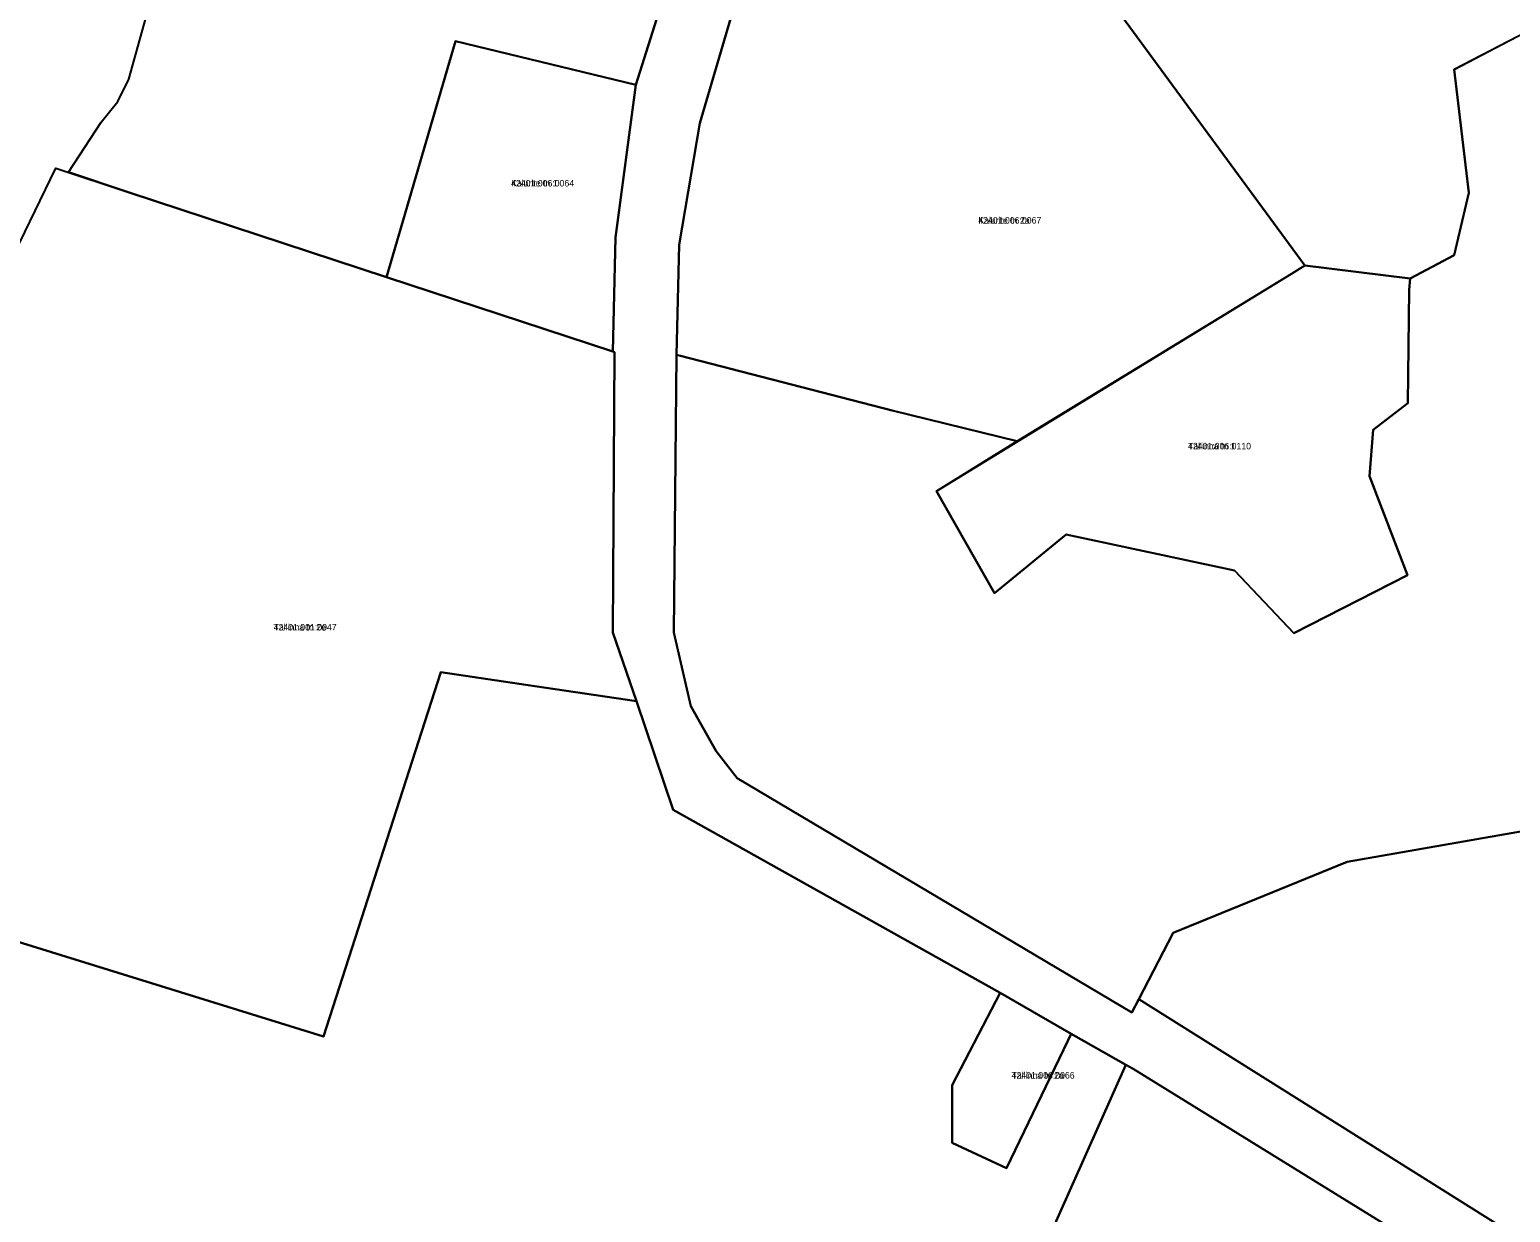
# Model space of a CAD drawing. Extents: x 595979 to 597983, y 6604231 to 6607350.
# Drawn here: x 596303.1 to 596644, y 6606612.5 to 6606884.7 of the extents above; entities that cross this region are included whole.
import ezdxf

# ---------------------------------------------------------------- set-up
doc = ezdxf.new("R2010")
doc.units = 0
for name, color, linetype in [('L_AADRESS', 7, 'Continuous'), ('PIIR', 7, 'Continuous'), ('TUNNUS', 7, 'Continuous')]:
    doc.layers.add(name, color=color, linetype=linetype)

msp = doc.modelspace()

# ---------------------------------------------------------------- linework, layer by layer
at = {"layer": 'PIIR'}
for points in [[(596470.43, 6606959.84), (596442.64, 6606872.04), (596401.1, 6606882.05), (596385.21, 6606827.71), (596326, 6606847.26), (596312.02, 6606851.88), (596319.53, 6606863.41), (596323.37, 6606868.18), (596325.88, 6606873.33), (596329.85, 6606887.36)], [(596909.1, 6606385.61), (596872.46, 6606418.2), (596861.56, 6606419.99), (596848.55, 6606432.38), (596762.79, 6606514.09), (596675.69, 6606572.34), (596638.27, 6606595.39), (596557.11, 6606645.51), (596555.44, 6606646.42), (596542.85, 6606653.57), (596526.52, 6606663), (596451.2, 6606705.15), (596442.76, 6606730.14), (596437.35, 6606745.96), (596437.73, 6606810.5), (596437.33, 6606810.61), (596437.96, 6606836.91), (596442.64, 6606872.04), (596470.43, 6606959.84)], [(596663.04, 6606703.09), (596606.42, 6606693.19), (596566.37, 6606676.82), (596558.45, 6606661.57), (596556.83, 6606658.51), (596465.96, 6606712.4), (596461.16, 6606718.64), (596455.33, 6606728.96), (596451.4, 6606745.94), (596451.96, 6606809.89), (596452.89, 6606809.63), (596501.66, 6606797.02), (596530.45, 6606789.96), (596511.82, 6606778.52), (596525.18, 6606754.97), (596541.67, 6606768.52), (596580.44, 6606760.19), (596594.14, 6606745.8), (596620.26, 6606759.16), (596611.54, 6606781.91), (596612.41, 6606792.61), (596620.34, 6606798.72), (596620.67, 6606824.8), (596620.92, 6606827.47), (596631.03, 6606832.78), (596634.38, 6606847.12), (596631, 6606875.52), (596643.75, 6606882.19), (596697.35, 6606910.02)], [(596464.47, 6606887.4), (596457.38, 6606863.19), (596452.59, 6606835.16), (596451.96, 6606809.89), (596451.4, 6606745.94), (596455.33, 6606728.96), (596461.16, 6606718.64), (596465.96, 6606712.4), (596556.83, 6606658.51), (596558.45, 6606661.57), (596684.47, 6606582.41), (596720.93, 6606558.63), (596736.24, 6606555.98), (596767.98, 6606529.52), (596797.47, 6606504.22), (596834.39, 6606472.9), (596889.22, 6606422.58)], [(596300.72, 6606835.57), (596309.11, 6606852.84), (596326, 6606847.26), (596385.21, 6606827.71), (596437.33, 6606810.61), (596437.73, 6606810.5), (596437.35, 6606745.96), (596442.76, 6606730.14), (596419.38, 6606733.61), (596397.75, 6606736.83), (596370.72, 6606652.99), (596288.27, 6606678.52)]]:
    msp.add_lwpolyline(points, dxfattribs=at)
for points in [[(596552.73, 6606890.18), (596558.1, 6606891.54), (596623.21, 6606907.76), (596659.33, 6606937.04), (596677.69, 6606947.28), (596694.97, 6606954.79), (596697.35, 6606910.02), (596631, 6606875.52), (596634.38, 6606847.12), (596631.03, 6606832.78), (596620.92, 6606827.47), (596596.63, 6606830.4)], [(596464.47, 6606887.4), (596548.26, 6606890.04), (596552.73, 6606890.18), (596596.63, 6606830.4), (596593.56, 6606828.51), (596530.45, 6606789.96), (596501.66, 6606797.02), (596452.89, 6606809.63), (596451.96, 6606809.89), (596452.59, 6606835.16), (596457.38, 6606863.19)], [(596401.1, 6606882.05), (596442.64, 6606872.04), (596437.96, 6606836.91), (596437.33, 6606810.61), (596385.21, 6606827.71)], [(596620.67, 6606824.8), (596620.34, 6606798.72), (596612.41, 6606792.61), (596611.54, 6606781.91), (596620.26, 6606759.16), (596594.14, 6606745.8), (596580.44, 6606760.19), (596541.67, 6606768.52), (596525.18, 6606754.97), (596511.82, 6606778.52), (596593.56, 6606828.51), (596596.63, 6606830.4), (596620.92, 6606827.47)], [(596370.72, 6606652.99), (596397.75, 6606736.83), (596419.38, 6606733.61), (596442.76, 6606730.14), (596451.2, 6606705.15), (596526.52, 6606663), (596515.45, 6606641.74), (596515.49, 6606628.51), (596528, 6606622.65), (596542.08, 6606651.96), (596542.85, 6606653.57), (596555.44, 6606646.42), (596540.01, 6606611.84), (596500.4, 6606523.05), (596466.73, 6606447.57), (596448.58, 6606437.61), (596381.08, 6606376.31), (596367.46, 6606391.27), (596242.07, 6606528), (596288.27, 6606678.52)], [(596733.13, 6606656.54), (596684.47, 6606582.41), (596558.45, 6606661.57), (596566.37, 6606676.82), (596606.42, 6606693.19), (596663.04, 6606703.09), (596708.41, 6606673.12)], [(596526.52, 6606663), (596542.85, 6606653.57), (596542.08, 6606651.96), (596528, 6606622.65), (596515.49, 6606628.51), (596515.45, 6606641.74)], [(596540.01, 6606611.84), (596555.44, 6606646.42), (596557.11, 6606645.51), (596638.27, 6606595.39), (596634.48, 6606573.71), (596630.11, 6606548.73), (596622.09, 6606502.86), (596609.49, 6606416.58), (596578.99, 6606421.05), (596577.86, 6606420.2), (596569.63, 6606421.41), (596552.3, 6606423.95), (596526.21, 6606427.77), (596477.99, 6606442.43), (596466.73, 6606447.57), (596500.4, 6606523.05)]]:
    msp.add_lwpolyline(points, close=True, dxfattribs=at)

# ---------------------------------------------------------------- texts
at = {"layer": 'L_AADRESS'}
for s, p in [('Kalurite tn 1', (596413.93, 6606848.62)), ('Kalurite tn 2a', (596521.48, 6606840.07)), ('Tallinna tn 1', (596569.76, 6606788.1)), ('Tallinna tn 2e', (596359.25, 6606746.41)), ('Tallinna tn 2a', (596529.15, 6606643.26))]:
    msp.add_text(s, height=1.5, dxfattribs=at).set_placement(p)
at = {"layer": 'TUNNUS'}
for s, p in [('42401:006:0064', (596413.93, 6606848.62)), ('42401:006:0067', (596521.48, 6606840.07)), ('42401:006:0110', (596569.76, 6606788.1)), ('42401:001:0047', (596359.25, 6606746.41)), ('42401:006:0066', (596529.15, 6606643.26))]:
    msp.add_text(s, height=1.5, dxfattribs=at).set_placement(p)

doc.saveas('drawing.dxf')
